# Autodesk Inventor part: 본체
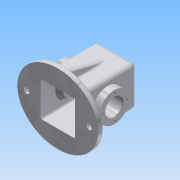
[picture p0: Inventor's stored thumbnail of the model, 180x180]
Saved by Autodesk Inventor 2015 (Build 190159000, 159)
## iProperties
Created: 2017-07
Part Number: 본체
Material: 알루미늄 6061
Document SubType Name: Modeling
Designer: Administrator
Density: 2.7 g/cm^3
Appearance: 알루미늄 - 평지
Author: Administrator
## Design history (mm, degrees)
sketch "스케치1"
  geometry: L1 (75, 65)-(-75, 65); L2 (-75, 65)-(-75, -65); L3 (-75, -65)-(75, -65); L4 (75, -65)-(75, 65); L5 (75, 65)-(-75, -65); L6 (-75, 65)-(75, -65); 2 further points; 1 other entity
  constraints: 12 end point, 3 horizontal, 2 midpoint, 2 parallel, 1 coincident, 1 perpendicular, 1 vertical, 2 other
  dimensions: "d0" = 75 horizontal distance of point (0, 0) L2.end; "d1" = 65 vertical distance of point (0, 0) L2.end
extrude "돌출1" new body sketch "스케치1" distance "d3" = 10; taper "d4" = 0 deg
sketch "스케치2"
  geometry: L1 (-37, -37)-(37, -37); L2 (37, -37)-(37, 37); L3 (37, 37)-(-37, 37); L4 (-37, 37)-(-37, -37); L5 (-37, -37)-(37, 37); L6 (37, -37)-(-37, 37); 1 further point
  constraints: 12 end point, 2 midpoint, 2 parallel, 1 horizontal, 1 perpendicular
  dimensions: "d5" = 74 distance of L1.start L1.end; "d6" = 74 distance of L1.end L2.end
extrude "돌출2" join sketch "스케치2" distance "d7" = 100; taper "d8" = 0 deg
sketch "스케치3"
  geometry: L1 (-37, 10)-(37, 10) reference; L2 (-37, 10)-(-37, 110) reference; L3 (37, 110)-(-37, 110) reference; L4 (37, 10)-(37, 110) reference; L5 (37, 110)-(-37, 110) reference; L6 (0, 110)-(0, 120); L7 (0, 120)-(20, 120); L8 (0, 110)-(20.875, 110); L9 (20, 120)-(20.875, 110); L10 (20.875, 110)-(20.875, 115.228); L11 (0, 120)-(-20, 120); L12 (0, 110)-(-20.875, 110); L13 (-20, 120)-(-20.875, 110); L14 (-20.875, 110)-(-20.875, 115.228); 1 further point
  constraints: 18 end point, 3 symmetric about line, 2 vertical, 1 collinear, 1 horizontal, 1 midpoint, 1 point on line
  dimensions: "d9" = 10 distance of L6.start L6.end; "d10" = 20 distance of L6.end L7.end; "d11" = 5 deg angle of L9 L10
extrude "돌출3" join sketch "스케치3" stored distance "d12" = 40; taper "d13" = 0 deg
sketch "스케치4"
  geometry: L1 (-28, -10)-(102, -10) reference; C1 r 27.5 at (37, 45); 1 further point
  constraints: 1 centre point, 1 vertical alignment
  dimensions: "d14" = 55 distance from line of L1 C1.centre; "d15" = 55 diameter of C1
extrude "돌출4" join sketch "스케치4" distance "d16" = 13; taper "d17" = 0 deg
node "작업 평면1"
sketch "스케치5"
  geometry: L1 (-32, 32)-(32, 32); L2 (32, 32)-(32, -32); L3 (32, -32)-(-32, -32); L4 (-32, -32)-(-32, 32); L5 (-32, 32)-(32, -32); L6 (32, 32)-(-32, -32); 1 further point
  constraints: 12 end point, 2 midpoint, 2 parallel, 1 horizontal, 1 perpendicular
  dimensions: "d18" = 64 distance of L2.end L3.end; "d19" = 64 distance of L3.end L1.start
extrude "돌출5" cut sketch "스케치5" distance "d20" = 105; taper "d21" = 0 deg
sketch "스케치6"
  geometry: L1 (-50, 82.5)-(-50, 27.5) reference; L2 (-37, 27.5)-(-37, 82.5) reference; L3 (-37, 27.5)-(-50, 27.5) reference; L4 (-37, 82.5)-(-50, 82.5) reference; L5 (-37, 82.5)-(-32, 82.5); L6 (-25, 75.5)-(-25, 55); L7 (-32, 0)-(-32, 105) reference; L8 (-32, 82.5)-(-25, 75.5); L9 (-32, 55)-(-25, 55); L10 (-32, 82.5)-(-32, 55); 1 further point
  constraints: 10 end point, 2 horizontal, 2 point on line, 1 collinear, 1 perpendicular
  dimensions: "d23" = 135 deg angle of L7 L8; "d24" = 7 distance from line of L7 L6.start; "d25" = 20.5 distance of L6.start L6.end
revolve "회전1" sketch "스케치6" stored, may be unused: angle "d26" = 90 deg
sketch "스케치7"
  geometry: C1 r 16 at (0, 0); C2 r 20.5 at (0, 0) reference; 1 further point
  constraints: 1 centre point, 1 concentric
  dimensions: "d27" = 32 diameter of C1
extrude "돌출6" cut sketch "스케치7" stored distance "d28" = 105; taper "d29" = 0 deg
chamfer "모따기1" distance "d30" = 1; stored, may be unused: second distance "d31" = 2, angle "d32" = 45 deg
sketch "스케치8"
  geometry: C1 r 17 at (0, 0) reference; 2 further points
  constraints: 1 horizontal alignment
  dimensions: "d33" = 22.5 distance of point (22.5, 0) C1.centre
hole "구멍1" sketch "스케치8" at (22.5, 0) diameter "d34" = 3.459; stored, may be unused: countersink angle "d38" = 90 deg, drill point angle "d40" = 118 deg; dims "d35" = 8, "d36" = 4, "d37" = 2, "d39" = 10
fillet "모깎기1" dims "d44" = 0.5
fillet "모깎기2" dims "d45" = 8
fillet "모깎기3" dims "d46" = 3
fillet "모깎기4" dims "d47" = 0.5
sketch "스케치9"
  geometry: L1 (102, 0)-(-28, 0) reference; L2 (-18, 0)-(0, 72.194); L3 (-28, 0)-(-28, -10); L4 (0, 0)-(0, 92) reference; L5 (-18, 0)-(0, 0); L6 (0, 72.194)-(0, 0); 1 further point
  constraints: 8 end point, 2 point on line, 1 horizontal, 1 perpendicular, 1 vertical
  dimensions: "d48" = 10 distance of L1.end L2.start; "d49" = 14 deg angle of L3 L2
extrude "돌출7" join sketch "스케치9" stored distance "d50" = 10; taper "d51" = 0 deg
node "작업 평면2"
fillet "모깎기7" dims "d54" = 3
fillet "모깎기8" dims "d55" = 3
fillet "모깎기9" dims "d62" = 3
fillet "모깎기10" dims "d63" = 3
sketch "스케치13"
  geometry: C1 r 14 at (17.251, 17); 1 further point
  constraints: 1 centre point, 1 coincident
  dimensions: "d64" = 28 diameter of C1
extrude "돌출10" cut sketch "스케치13" distance "d65" = 4; taper "d66" = 0 deg
sketch "스케치14"
  geometry: C1 r 10.5 at (0, 0); 1 further point
  constraints: 1 centre point, 1 coincident
  dimensions: "d67" = 21 diameter of C1
extrude "돌출11" cut sketch "스케치14" distance "d68" = 20; taper "d69" = 0 deg
sketch "스케치15"
  geometry: C1 r 5 at (-58, 0); 1 further point
  constraints: 1 centre point, 1 horizontal alignment
  dimensions: "d70" = 58 distance of point (0, 0) C1.centre; "d71" = 10 diameter of C1
extrude "돌출12" cut sketch "스케치15" stored distance "d72" = 20; taper "d73" = 0 deg
fillet "모깎기11" dims "d74" = 3
fillet "모깎기12" dims "d75" = 3
node "솔리드1"
mirror "대칭1"
mirror "대칭2"
pattern_circular "원형 패턴1" dims angle "d42" = 360 deg
mirror "대칭3"
mirror "대칭4"
mirror "대칭5"
mirror "대칭6"
node "투영된 루프1"
node "투영된 루프2"
